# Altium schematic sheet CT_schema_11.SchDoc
size 274 x 160 mm
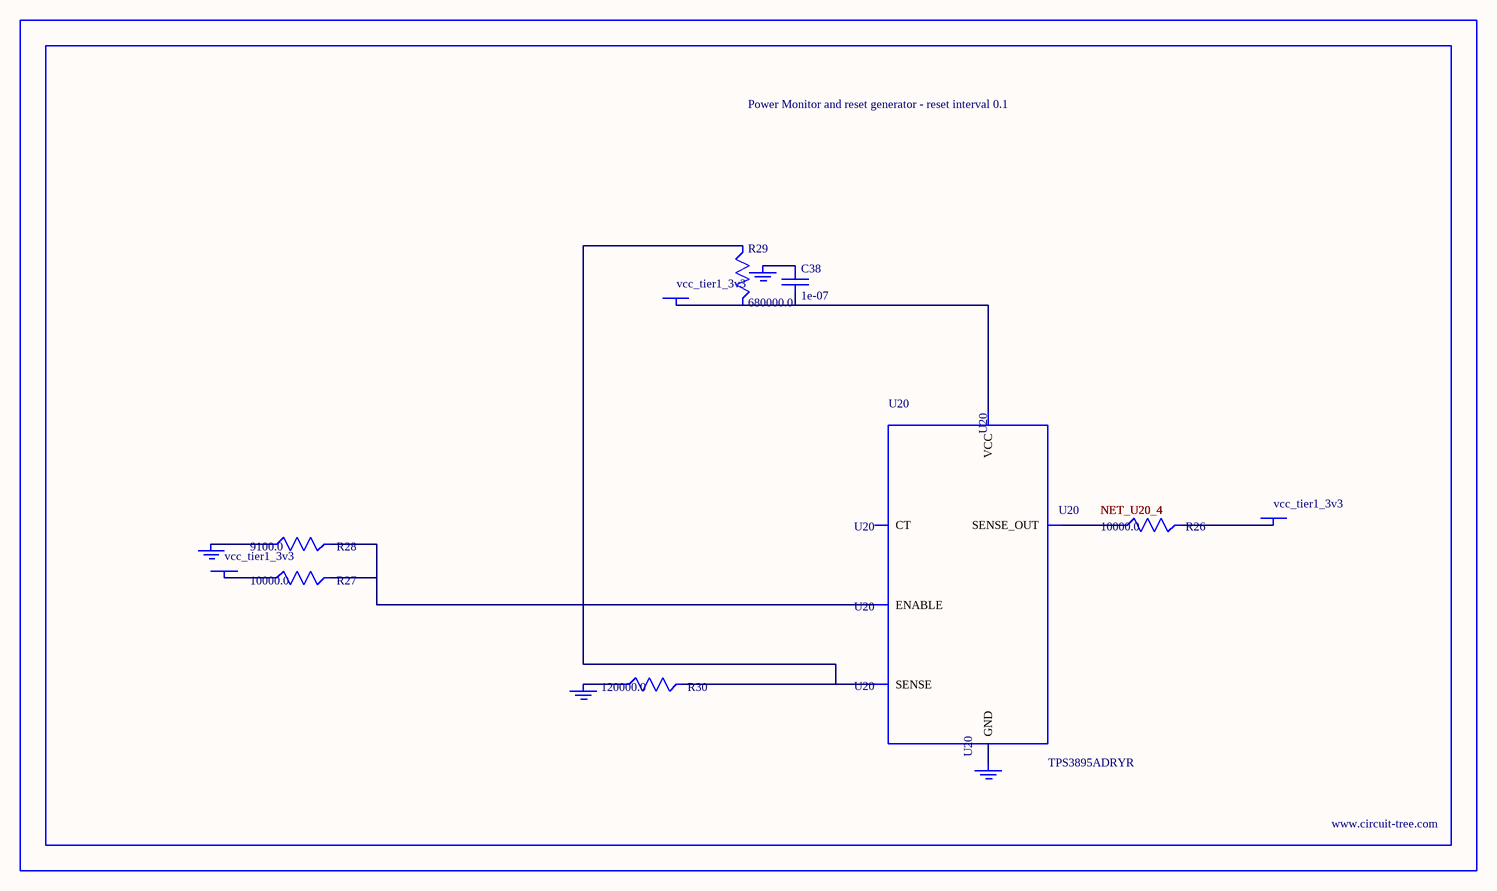
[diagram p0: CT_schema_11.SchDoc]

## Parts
BORDER10  (no value)
C38  1e-07  [C0402]
GND_INSTANCE_10_0  (no value)
GND_INSTANCE_10_1  (no value)
GND_INSTANCE_10_2  (no value)
GND_INSTANCE_10_3  (no value)
POWER_INSTANCE_10_0  vcc_tier1_3v3
POWER_INSTANCE_10_1  vcc_tier1_3v3
POWER_INSTANCE_10_2  vcc_tier1_3v3
R26  10000.0  [R0603]
R27  10000.0  [R0603]
R28  9100.0  [R0603]
R29  680000.0  [R0603]
R30  120000.0  [R0603]
U20  TPS3895ADRYR  [SON-6]

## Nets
NetC38_1: C38.1 GND_INSTANCE_10_2.0(GND)
NetC38_2: C38.2 POWER_INSTANCE_10_2.0(PWR) R29.2 U20.6(VCC)
NetGND_INSTANCE_10_0_0: GND_INSTANCE_10_0.0(GND) R28.1
NetGND_INSTANCE_10_1_0: GND_INSTANCE_10_1.0(GND) R30.1
NetGND_INSTANCE_10_3_0: GND_INSTANCE_10_3.0(GND) U20.2(GND)
NetPOWER_INSTANCE_10_0_0: POWER_INSTANCE_10_0.0(PWR) R27.1
NetPOWER_INSTANCE_10_1_0: POWER_INSTANCE_10_1.0(PWR) R26.2
NetR26_1: R26.1 U20.4(SENSE_OUT)
NetR27_2: R27.2 R28.2 U20.1(ENABLE)
NetR29_1: R29.1 R30.2 U20.3(SENSE)

Not connected (* = marked no-connect by the designer): U20 5(CT)

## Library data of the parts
BORDER10 = BORDER_PAGE10
C38 = C0402C104K3RACTU
GND_INSTANCE_10_0-GND_INSTANCE_10_3 = GND
POWER_INSTANCE_10_0-POWER_INSTANCE_10_2 = PWR
R26 R27 = RC0603JR-0710KL
R28 = RC0603JR-079K1L
R29 = RC0603JR-07680KL
R30 = RC0603JR-07120KL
